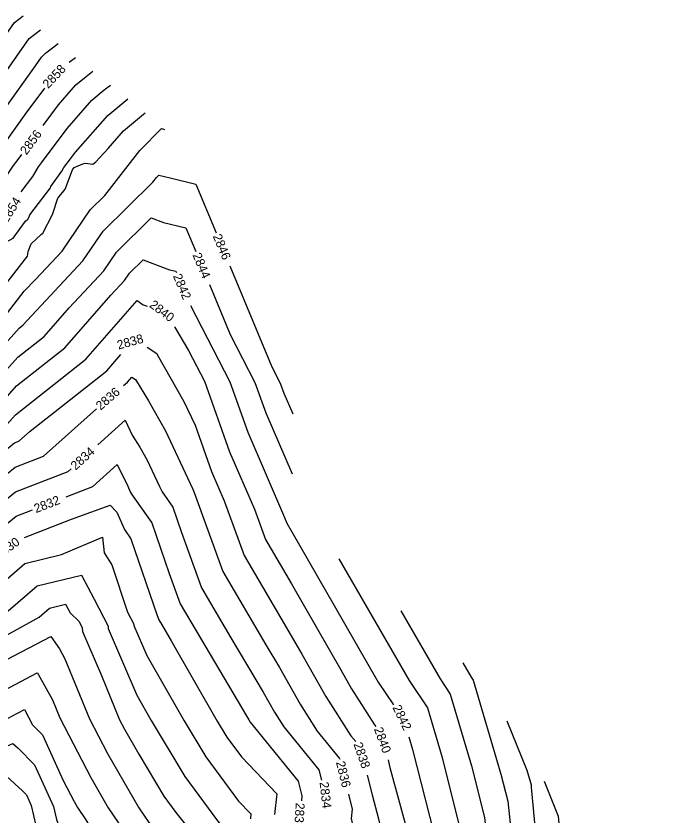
# Model space of a CAD drawing. Extents: x 1326424 to 1329294, y 1001359 to 1003823.
# Drawn here: x 1328281.6 to 1328428.4, y 1003237.8 to 1003415.6 of the extents above; entities that cross this region are included whole.
import ezdxf

# ---------------------------------------------------------------- set-up
doc = ezdxf.new("R2010")
doc.units = 0
doc.layers.add('Prop Rem of Exist Asph Pvmt', color=7, linetype='Continuous')
doc.layers.add('Scratch_Level_3', color=7, linetype='Continuous')

msp = doc.modelspace()

# ---------------------------------------------------------------- linework, layer by layer
at = {"layer": 'Prop Rem of Exist Asph Pvmt'}
for points in [[(1328250.63, 1003358.87), (1328253.13, 1003360.51), (1328262.47, 1003371.35), (1328267.52, 1003377.83), (1328268.19, 1003379.44), (1328272.34, 1003385.53), (1328285.97, 1003404.54), (1328287.35, 1003406.41), (1328287.93, 1003407.06), (1328288.22, 1003407.3), (1328291.01, 1003409.45)], [(1328230.38, 1003296.58), (1328234.33, 1003297.42), (1328239.44, 1003300.08), (1328259.16, 1003310.16), (1328264.63, 1003312.8), (1328265.36, 1003313.14), (1328266.18, 1003313.69), (1328278.92, 1003323.93), (1328281.53, 1003326.82), (1328297.21, 1003339.19), (1328308.61, 1003352.26), (1328310, 1003351.34), (1328310.9, 1003351)], [(1328316.93, 1003346.44), (1328320.07, 1003341.18), (1328323.61, 1003334.3), (1328329.23, 1003318.58), (1328334.76, 1003305.85), (1328337.21, 1003299.11), (1328343.02, 1003289.21), (1328353.99, 1003270.03), (1328356.35, 1003265.87), (1328361.47, 1003257.86), (1328361.77, 1003257.42)], [(1328237.22, 1003242.85), (1328237.44, 1003242.9), (1328243.76, 1003246.22), (1328268.04, 1003259.38), (1328268.09, 1003259.4), (1328268.18, 1003259.44), (1328279.09, 1003265.54), (1328285.07, 1003268.72), (1328286.38, 1003269.4), (1328286.61, 1003269.09), (1328289.76, 1003263.36), (1328291.39, 1003259.38), (1328298.33, 1003246.11), (1328302.19, 1003239.38), (1328307.88, 1003230.97)], [(1328364.5, 1003250), (1328364.93, 1003248.31), (1328369.2, 1003232.62), (1328370.48, 1003226.66), (1328371.13, 1003221.21), (1328372.06, 1003213.09), (1328374.82, 1003193.66), (1328375.09, 1003191.59), (1328375.15, 1003190.74), (1328380.65, 1003170.61), (1328380.78, 1003170.09), (1328381.76, 1003168.54), (1328390.39, 1003154.55)]]:
    msp.add_lwpolyline(points, dxfattribs=at)
at = {"layer": 'Scratch_Level_3'}
for points in [[(1328259.82, 1003385.04), (1328260.15, 1003385.41), (1328263.4, 1003388.82), (1328265.92, 1003392.23), (1328281.33, 1003414.14), (1328283.24, 1003415.6)], [(1328255.44, 1003371.57), (1328264.15, 1003381.68), (1328266.09, 1003384.18), (1328266.35, 1003384.8), (1328267.95, 1003387.14), (1328275.75, 1003398.02), (1328284.58, 1003410.57), (1328287.12, 1003412.52)], [(1328293.5, 1003405.3), (1328294.9, 1003406.37)], [(1328287.7, 1003391.22), (1328291.13, 1003395.86), (1328295.01, 1003400.25), (1328296.94, 1003401.87), (1328298.79, 1003403.29)], [(1328282.8, 1003376.44), (1328285.4, 1003379.85), (1328286.65, 1003381.99), (1328287.34, 1003382.91), (1328293.02, 1003390.58), (1328298.55, 1003396.85), (1328301.3, 1003399.15), (1328302.68, 1003400.21)], [(1328214.67, 1003337.91), (1328215.8, 1003337.89), (1328220.1, 1003338.82), (1328231.6, 1003341.29), (1328237.62, 1003344.02), (1328254.38, 1003355.53), (1328258.2, 1003358.03), (1328260.78, 1003361.03), (1328268.94, 1003371.49), (1328270.03, 1003374.09), (1328276.74, 1003383.92), (1328283.94, 1003393.97), (1328288.04, 1003399.51)], [(1328276.61, 1003362.65), (1328276.81, 1003363.7), (1328279.57, 1003365.34), (1328280.99, 1003366.15), (1328283.75, 1003369.94), (1328284.29, 1003370.34), (1328284.56, 1003370.87), (1328284.71, 1003371.33), (1328289.33, 1003377.32), (1328289.38, 1003377.65), (1328291.86, 1003381.05), (1328292.33, 1003381.86), (1328293.8, 1003383.82), (1328294.91, 1003385.31), (1328302.08, 1003393.44), (1328305.65, 1003396.44), (1328306.57, 1003397.14)], [(1328276.48, 1003352.28), (1328284.19, 1003362.15), (1328284.31, 1003362.59), (1328284.34, 1003363.19), (1328285.01, 1003364.86), (1328287.33, 1003367.01), (1328287.65, 1003367.24), (1328289.75, 1003371.45), (1328290.98, 1003375.04), (1328291, 1003375.07), (1328291.01, 1003375.12), (1328292.57, 1003377.02), (1328294.23, 1003381.34), (1328294.57, 1003381.87), (1328296.52, 1003382.68), (1328297.07, 1003382.82), (1328298.74, 1003382.59), (1328299.37, 1003383.03), (1328301.26, 1003385.13), (1328302.18, 1003386.14), (1328305.62, 1003390.04), (1328310.01, 1003393.72), (1328310.45, 1003394.06)], [(1328266.33, 1003334.82), (1328267.25, 1003335.44), (1328267.26, 1003335.45), (1328267.29, 1003335.49), (1328278.65, 1003348.04), (1328279.75, 1003349.54), (1328283.49, 1003354.33), (1328286.03, 1003356.97), (1328291.94, 1003363.27), (1328298.18, 1003372.43), (1328301.46, 1003375.68), (1328309.22, 1003385.68), (1328314.06, 1003390.53), (1328314.76, 1003390.35)], [(1328204.4, 1003333.46), (1328211.82, 1003333.22), (1328215.98, 1003333.13), (1328218.45, 1003333.57), (1328232.76, 1003336.64), (1328242.46, 1003341.05), (1328256.47, 1003350.67), (1328259.32, 1003352.45), (1328262.1, 1003354.96), (1328263.3, 1003356.35), (1328264.18, 1003357.41), (1328265.71, 1003359.17), (1328270.36, 1003365.15), (1328271.87, 1003368.74), (1328281.13, 1003382.31), (1328281.91, 1003383.39), (1328282.94, 1003384.79)], [(1328257.66, 1003323.79), (1328257.92, 1003323.91), (1328266.98, 1003330.01), (1328270.17, 1003332.57), (1328282.36, 1003346.12), (1328283.27, 1003346.84), (1328284.14, 1003347.83), (1328296.56, 1003361.08), (1328301.09, 1003367.72), (1328312.1, 1003378.63), (1328312.92, 1003379.68), (1328313.43, 1003380.2), (1328316.01, 1003379.54), (1328321.71, 1003378.17), (1328326.21, 1003367.36)], [(1328247.85, 1003314.33), (1328254.9, 1003317.72), (1328260.4, 1003320.32), (1328266.72, 1003324.57), (1328273.09, 1003329.69), (1328282.08, 1003339.69), (1328287.92, 1003344.29), (1328293.46, 1003350.65), (1328301.19, 1003358.89), (1328304.01, 1003363.02), (1328311.77, 1003370.71), (1328314.51, 1003369.67), (1328319.48, 1003368.47), (1328321.68, 1003363.19)], [(1328238.69, 1003305.12), (1328259.77, 1003315.26), (1328262.88, 1003316.73), (1328266.45, 1003319.13), (1328276.01, 1003326.81), (1328281.8, 1003333.25), (1328292.56, 1003341.74), (1328302.79, 1003353.47), (1328305.82, 1003356.7), (1328306.93, 1003358.32), (1328309.97, 1003361.33), (1328315.83, 1003359.11), (1328317.25, 1003358.77), (1328317.36, 1003358.52)], [(1328329.29, 1003359.97), (1328338.64, 1003337.52), (1328340.5, 1003333.91), (1328341.31, 1003331.62), (1328343.3, 1003327.04)], [(1328324.76, 1003355.8), (1328329.36, 1003344.74), (1328334.87, 1003334.04), (1328337.29, 1003327.28), (1328343.18, 1003313.69)], [(1328320.5, 1003351.17), (1328329.24, 1003334.17), (1328333.26, 1003322.93), (1328341.47, 1003304), (1328341.95, 1003302.69), (1328343.07, 1003300.78), (1328352.48, 1003284.35), (1328362.32, 1003267.31), (1328365.7, 1003262.24)], [(1328310.85, 1003341.88), (1328312.98, 1003340.48), (1328313.11, 1003340.26), (1328319.05, 1003329.77), (1328321.53, 1003324.49), (1328325.2, 1003314.24), (1328328.04, 1003307.69), (1328332.46, 1003295.52), (1328342.96, 1003277.64), (1328345.28, 1003273.59), (1328350.63, 1003264.14), (1328356.22, 1003255.41), (1328357.3, 1003254.08)], [(1328220.79, 1003289.26), (1328235.17, 1003292.32), (1328244.85, 1003297.34), (1328266.36, 1003308.35), (1328268.28, 1003309.97), (1328281.32, 1003320.58), (1328282.31, 1003320.96), (1328284.81, 1003323.2), (1328301.86, 1003336.64), (1328305, 1003340.24)], [(1328305.59, 1003333.37), (1328306.51, 1003334.09), (1328307.47, 1003335.21), (1328308.25, 1003334.7), (1328311.16, 1003329.94), (1328314.94, 1003323.26), (1328320.97, 1003310.45), (1328321.17, 1003309.89), (1328321.33, 1003309.54), (1328327.72, 1003291.93), (1328337.27, 1003275.66), (1328340.3, 1003270.56), (1328344.92, 1003262.41), (1328348.76, 1003256.41), (1328353.72, 1003250.32), (1328353.76, 1003250.15)], [(1328212.71, 1003283.27), (1328216.06, 1003282.88), (1328220.92, 1003284.01), (1328236, 1003287.21), (1328250.25, 1003294.61), (1328266.73, 1003303.04), (1328271.4, 1003306.98), (1328281.44, 1003315.14), (1328287.79, 1003317.6), (1328299.55, 1003328.14)], [(1328299.89, 1003320.18), (1328305.94, 1003325.61), (1328307.55, 1003322.33), (1328309.2, 1003319.63), (1328310.83, 1003316.75), (1328313.61, 1003310.84), (1328314.18, 1003309.71), (1328316.56, 1003306.3), (1328318.44, 1003300.85), (1328322.98, 1003288.34), (1328329.52, 1003277.19), (1328336.68, 1003265.12), (1328339.2, 1003260.68), (1328341.29, 1003257.41), (1328349.12, 1003247.81), (1328349.7, 1003245.5)], [(1328203.72, 1003279.02), (1328216.42, 1003277.52), (1328228.82, 1003280.4), (1328236.84, 1003282.11), (1328255.66, 1003291.88), (1328267.1, 1003297.73), (1328274.52, 1003303.99), (1328281.56, 1003309.71), (1328293.26, 1003314.24), (1328293.93, 1003314.84)], [(1328292.79, 1003308.59), (1328298.74, 1003310.89), (1328304.17, 1003315.76), (1328306.53, 1003310.97), (1328307.08, 1003309.69), (1328307.19, 1003309.58), (1328307.26, 1003309.41), (1328311.91, 1003302.75), (1328315.78, 1003291.52), (1328318.23, 1003284.75), (1328321.78, 1003278.72), (1328333.07, 1003259.68), (1328333.49, 1003258.95), (1328333.83, 1003258.41), (1328344.52, 1003245.3), (1328345.34, 1003242.01), (1328345.21, 1003240.89)], [(1328194.36, 1003274.8), (1328216.77, 1003272.16), (1328236.73, 1003276.8), (1328237.68, 1003277), (1328261.07, 1003289.15), (1328267.47, 1003292.42), (1328277.64, 1003301), (1328281.67, 1003304.28), (1328285.33, 1003305.7)], [(1328283.55, 1003299.53), (1328294.03, 1003303.59), (1328302.62, 1003306.69), (1328304.08, 1003305.14), (1328305.78, 1003301.33), (1328307.26, 1003299.21), (1328313.12, 1003282.19), (1328313.49, 1003281.16), (1328314.03, 1003280.24), (1328316.24, 1003276.52), (1328326.46, 1003258.67), (1328328.6, 1003255.09), (1328331.86, 1003250.69), (1328339.72, 1003242.44), (1328339.2, 1003237.84)], [(1328276.12, 1003287.31), (1328283.64, 1003293.72), (1328291.75, 1003295.71), (1328300.9, 1003299.63), (1328301.31, 1003296.08), (1328302.99, 1003293.46), (1328306.52, 1003282.91), (1328307.92, 1003280.2), (1328307.93, 1003279.96), (1328310.81, 1003273.25), (1328319.12, 1003258.75), (1328323.93, 1003250.7), (1328331.24, 1003240.84), (1328333.96, 1003237.98), (1328333.84, 1003236.89)], [(1328353.57, 1003294.77), (1328369.22, 1003267.69), (1328373.27, 1003261.61), (1328376.54, 1003250.52), (1328380.83, 1003233.57), (1328382.25, 1003220.44), (1328382.44, 1003218.73), (1328382.7, 1003216.92), (1328383.86, 1003201.35)], [(1328267.53, 1003275.82), (1328267.99, 1003276.06), (1328272.38, 1003279.07), (1328279.89, 1003283.21), (1328286.39, 1003288.75), (1328296.25, 1003291.17), (1328299.07, 1003285.81), (1328299.07, 1003285.8), (1328302.17, 1003279.82), (1328302.18, 1003279.29), (1328308.59, 1003264.4), (1328311.78, 1003258.82), (1328319.25, 1003246.32), (1328326.55, 1003236.48), (1328328.14, 1003234.5), (1328328.68, 1003233.03)], [(1328257.4, 1003264.97), (1328257.79, 1003265.18), (1328268.01, 1003270.5), (1328274.95, 1003275.25), (1328286.8, 1003281.78), (1328289.14, 1003283.78), (1328292.69, 1003284.65), (1328293.71, 1003282.72), (1328295.71, 1003280.81), (1328296.42, 1003279.43), (1328296.44, 1003278.62), (1328300.67, 1003268.77), (1328304.7, 1003258.95), (1328305.79, 1003256.86), (1328309, 1003251.27), (1328314.57, 1003241.94), (1328317.27, 1003238.29), (1328321.35, 1003233.22)], [(1328367.37, 1003283.2), (1328376.12, 1003268.07), (1328378.38, 1003264.67), (1328383.1, 1003248.68), (1328386, 1003237.2), (1328387.16, 1003226.47), (1328387.73, 1003220.19), (1328387.48, 1003215.42), (1328388.37, 1003203.55), (1328391.59, 1003195.15), (1328393.98, 1003190.56), (1328394.94, 1003188.83)], [(1328247.4, 1003253.76), (1328262.96, 1003262.3), (1328268.04, 1003264.95), (1328276.82, 1003270.96), (1328277.46, 1003271.32), (1328277.8, 1003271.5), (1328289.38, 1003277.46), (1328291.34, 1003274.76), (1328292.56, 1003272.53), (1328298.05, 1003259.16), (1328302.06, 1003251.48), (1328309.01, 1003239.37), (1328311.24, 1003236.07), (1328314.25, 1003232.33)], [(1328381.17, 1003271.64), (1328383.01, 1003268.45), (1328383.49, 1003267.73), (1328389.65, 1003246.85), (1328391.17, 1003240.82), (1328391.78, 1003235.19), (1328393.05, 1003221.37), (1328392.5, 1003210.85), (1328392.73, 1003207.73), (1328393.58, 1003205.52), (1328399.55, 1003194.01), (1328403.74, 1003186.5), (1328408.9, 1003177.55)], [(1328224.86, 1003234.7), (1328237.7, 1003237.6), (1328249.23, 1003243.66), (1328266.35, 1003252.93), (1328270.09, 1003254.6), (1328276.47, 1003257.38), (1328280.72, 1003259.76), (1328283.56, 1003261.27), (1328285.34, 1003257.86), (1328287.54, 1003255.61), (1328292.13, 1003245.47), (1328294.6, 1003240.74), (1328295.37, 1003239.4), (1328297.24, 1003236.65), (1328300.74, 1003230.73)], [(1328390.94, 1003258.72), (1328395.39, 1003247.76), (1328396.2, 1003245.01), (1328396.35, 1003244.45), (1328396.4, 1003243.92), (1328398.36, 1003222.54), (1328397.84, 1003212.57), (1328399.33, 1003208.64), (1328405.13, 1003197.46), (1328411.84, 1003185.44), (1328415.71, 1003178.71), (1328426.7, 1003173), (1328428.42, 1003171.94)], [(1328369.17, 1003255.13), (1328369.99, 1003252.35), (1328375.66, 1003229.95), (1328375.9, 1003227.75), (1328377.25, 1003215.91), (1328379.04, 1003203.3), (1328379.65, 1003195.2), (1328381.52, 1003190.31), (1328385.04, 1003177.45), (1328389.62, 1003168.84), (1328395.23, 1003159.75)], [(1328213.33, 1003227.58), (1328216.92, 1003227.9), (1328219.11, 1003228.25), (1328224.5, 1003229.25), (1328237.96, 1003232.29), (1328254.71, 1003241.1), (1328264.65, 1003246.48), (1328272.09, 1003249.8), (1328280.97, 1003253.67), (1328282.11, 1003252.64), (1328285.76, 1003248.92), (1328289.97, 1003239.61), (1328290.64, 1003236.73), (1328292.62, 1003231.4), (1328293.24, 1003230.34)], [(1328200.97, 1003221.82), (1328204.15, 1003221.69), (1328214.95, 1003222.66), (1328220.6, 1003223.56), (1328234.52, 1003226.15), (1328238.21, 1003226.99), (1328260.18, 1003238.54), (1328262.95, 1003240.04), (1328274.09, 1003244.99), (1328278.77, 1003247.04), (1328283.07, 1003243.15), (1328283.98, 1003242.22), (1328285.03, 1003239.89), (1328286.59, 1003233.17), (1328286.76, 1003232.71)], [(1328359.86, 1003246.64), (1328360.95, 1003242.26), (1328362.41, 1003236.88), (1328365.3, 1003223.45), (1328366.76, 1003211.19), (1328366.87, 1003210.26), (1328367.18, 1003208.04), (1328369.39, 1003191.39), (1328369.88, 1003184.59), (1328373.77, 1003170.34), (1328374.75, 1003166.63), (1328381.81, 1003155.41), (1328384.53, 1003151.01)], [(1328399.25, 1003245.32), (1328402.41, 1003237.53), (1328403.67, 1003223.72), (1328403.36, 1003217.76), (1328407.17, 1003207.72), (1328410.7, 1003200.91), (1328411.74, 1003199.05)], [(1328355.69, 1003242.39), (1328356.52, 1003239.06), (1328356.28, 1003236.94), (1328359.67, 1003221.91), (1328360.23, 1003219.84), (1328361.58, 1003209.63), (1328362.85, 1003197.56), (1328363.69, 1003191.2), (1328364.61, 1003178.44), (1328366.9, 1003170.07), (1328368.71, 1003163.17), (1328376.29, 1003151.13), (1328378.76, 1003146.56)]]:
    msp.add_lwpolyline(points, dxfattribs=at)

# ---------------------------------------------------------------- texts
at = {"layer": 'Prop Rem of Exist Asph Pvmt'}
for rotation, p in [(322.8342, (1328311.19, 1003350.97)), (290.2073, (1328361.34, 1003256.9))]:
    msp.add_text('2840', height=2, rotation=rotation, dxfattribs=at).set_placement(p)
at = {"layer": 'Scratch_Level_3'}
for s, rotation, p in [('2858', 46.6463, (1328288.82, 1003399.33)), ('2856', 53.5058, (1328283.99, 1003384.53)), ('2854', 57.8741, (1328279.72, 1003369.42)), ('2846', 292.6066, (1328325.45, 1003366.59)), ('2844', 292.6066, (1328320.92, 1003362.42)), ('2842', 293.1198, (1328316.57, 1003357.73)), ('2838', 15.6158, (1328304.48, 1003341.34)), ('2836', 40.86, (1328300.49, 1003327.73)), ('2834', 41.8743, (1328294.93, 1003314.4)), ('2832', 21.1574, (1328286.11, 1003304.93)), ('2830', 35.5466, (1328277.85, 1003294.63)), ('2842', 296.0036, (1328365.45, 1003261.69)), ('2838', 288.9575, (1328356.79, 1003253.55)), ('2836', 283.9519, (1328352.9, 1003249.48)), ('2834', 276.5876, (1328349.26, 1003245.03)), ('2832', 266.54, (1328343.97, 1003240.52))]:
    msp.add_text(s, height=2, rotation=rotation, dxfattribs=at).set_placement(p)

doc.saveas('drawing.dxf')
